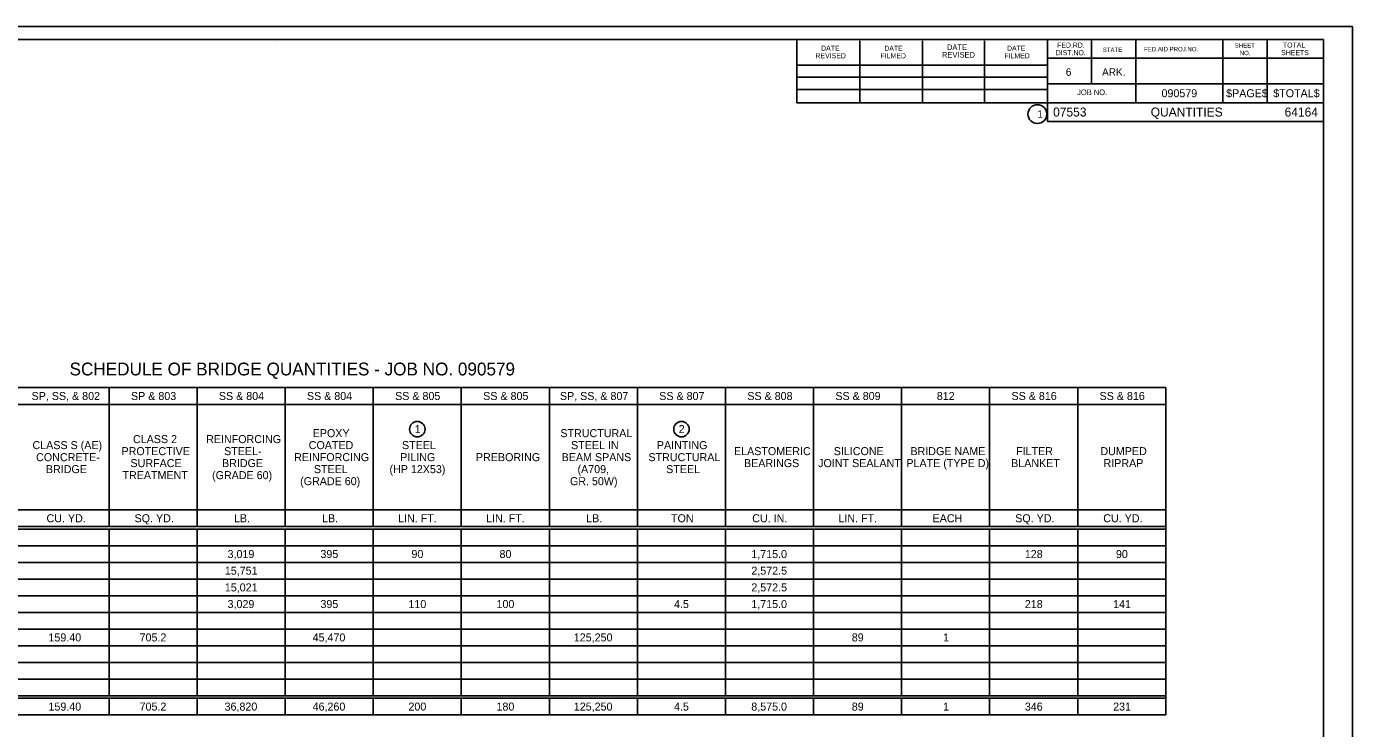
# Model space of a CAD drawing. Extents: x -1.3 to 32.1, y -0.4 to 20.7.
# Drawn here: x 11.36 to 32.07, y 9.78 to 20.75 of the extents above; entities that cross this region are included whole.
import ezdxf

# ---------------------------------------------------------------- set-up
doc = ezdxf.new("R2010")
doc.units = 0
for name, color, linetype in [('Level 1', 7, 'Continuous'), ('Level 1a', 7, 'Continuous'), ('Level 3', 7, 'Continuous'), ('Level 4', 7, 'Continuous'), ('Level 63', 7, 'Continuous'), ('R_Border', 7, 'Continuous')]:
    doc.layers.add(name, color=color, linetype=linetype)

msp = doc.modelspace()

# ---------------------------------------------------------------- linework, layer by layer
at = {"layer": 'Level 1'}
for p, q in [((-0.001, 20.545), (31.617, 20.545)), ((23.391, 19.557), (23.391, 20.545)), ((24.377, 19.557), (24.377, 20.525)), ((25.353, 19.557), (25.353, 20.525)), ((26.321, 19.557), (26.321, 20.525)), ((27.307, 20.545), (27.307, 19.265)), ((27.991, 20.545), (27.991, 19.851)), ((28.685, 20.545), (28.685, 19.557)), ((30.043, 20.545), (30.043, 19.557)), ((30.737, 20.545), (30.737, 19.557)), ((31.617, -0.001), (31.617, 20.545)), ((23.391, 20.143), (27.307, 20.143)), ((31.617, 20.251), (27.307, 20.251)), ((31.617, 20.253), (31.617, 20.253)), ((23.391, 19.957), (27.307, 19.957)), ((23.391, 19.557), (23.391, 19.763)), ((23.391, 19.763), (27.307, 19.763)), ((31.617, 19.851), (27.307, 19.851)), ((31.617, 19.557), (23.391, 19.557))]:
    msp.add_line(p, q, dxfattribs=at)
msp.add_circle((27.147, 19.379), 0.147, dxfattribs=at)
at = {"layer": 'Level 1a'}
msp.add_line((27.307, 19.265), (31.617, 19.265), dxfattribs=at)
at = {"layer": 'Level 3'}
msp.add_line((15.251, 20.519), (15.251, 20.519), dxfattribs=at)
msp.add_line((15.251, 20.519), (15.251, 20.519), dxfattribs=at)
at = {"layer": 'Level 4'}
for p, q in [((29.152, 15.107), (1.652, 15.107)), ((12.652, 15.107), (12.652, 12.937)), ((14.027, 15.107), (14.027, 12.937)), ((15.402, 15.107), (15.402, 12.937)), ((16.777, 15.107), (16.777, 12.937)), ((18.152, 15.107), (18.152, 12.937)), ((19.527, 15.107), (19.527, 12.937)), ((20.902, 15.107), (20.902, 12.937)), ((20.902, 15.107), (20.902, 12.937)), ((22.277, 15.107), (22.277, 12.937)), ((23.652, 15.107), (23.652, 12.937)), ((23.652, 15.107), (23.652, 12.937)), ((25.027, 15.107), (25.027, 12.937)), ((25.027, 15.107), (25.027, 12.937)), ((26.402, 15.107), (26.402, 12.937)), ((26.402, 15.107), (26.402, 12.937)), ((27.777, 15.107), (27.777, 12.937)), ((27.777, 15.107), (27.777, 12.937)), ((29.152, 15.107), (29.152, 9.996)), ((29.152, 14.846), (6.369, 14.846)), ((29.152, 13.198), (6.369, 13.198)), ((29.152, 12.937), (1.652, 12.937)), ((29.152, 12.899), (1.652, 12.899)), ((12.652, 12.899), (12.652, 10.295)), ((14.027, 12.899), (14.027, 10.295)), ((15.402, 12.899), (15.402, 10.295)), ((16.777, 12.899), (16.777, 10.295)), ((18.152, 12.899), (18.152, 10.295)), ((19.527, 12.899), (19.527, 10.295)), ((20.902, 12.899), (20.902, 10.295)), ((20.902, 12.899), (20.902, 10.295)), ((22.277, 12.899), (22.277, 10.295)), ((23.652, 12.899), (23.652, 10.295)), ((23.652, 12.899), (23.652, 10.295)), ((25.027, 12.899), (25.027, 10.295)), ((25.027, 12.899), (25.027, 10.295)), ((26.402, 12.899), (26.402, 10.295)), ((26.402, 12.899), (26.402, 10.295)), ((27.777, 12.899), (27.777, 10.295)), ((27.777, 12.899), (27.777, 10.295)), ((29.152, 12.639), (2.725, 12.639)), ((29.152, 12.378), (2.725, 12.378)), ((29.152, 12.118), (2.725, 12.118)), ((29.152, 11.857), (2.725, 11.857)), ((29.152, 11.857), (2.725, 11.857)), ((29.152, 11.597), (2.725, 11.597)), ((29.152, 11.337), (2.725, 11.337)), ((29.152, 11.076), (2.725, 11.076)), ((29.152, 10.816), (2.725, 10.816)), ((29.152, 10.555), (2.725, 10.555)), ((29.152, 10.295), (1.652, 10.295)), ((29.152, 10.257), (1.652, 10.257)), ((12.652, 10.257), (12.652, 9.996)), ((14.027, 10.257), (14.027, 9.996)), ((15.402, 10.257), (15.402, 9.996)), ((16.777, 10.257), (16.777, 9.996)), ((18.152, 10.257), (18.152, 9.996)), ((19.527, 10.257), (19.527, 9.996)), ((20.902, 10.257), (20.902, 9.996)), ((20.902, 10.257), (20.902, 9.996)), ((22.277, 10.257), (22.277, 9.996)), ((23.652, 10.257), (23.652, 9.996)), ((23.652, 10.257), (23.652, 9.996)), ((25.027, 10.257), (25.027, 9.996)), ((25.027, 10.257), (25.027, 9.996)), ((26.402, 10.257), (26.402, 9.996)), ((26.402, 10.257), (26.402, 9.996)), ((27.777, 10.257), (27.777, 9.996)), ((27.777, 10.257), (27.777, 9.996)), ((29.152, 9.996), (1.652, 9.996))]:
    msp.add_line(p, q, dxfattribs=at)
for centre in [(17.465, 14.459), (21.59, 14.459)]:
    msp.add_circle(centre, 0.121, dxfattribs=at)
at = {"layer": 'Level 63'}
msp.add_lwpolyline([(-1.263, -0.201), (32.067, -0.201), (32.067, 20.747), (-1.263, 20.747)], close=True, dxfattribs=at)

# ---------------------------------------------------------------- texts
at = {"layer": 'Level 1'}
for s, height, p in [('TOTAL', 0.0782, (30.981, 20.417)), ('REVISED', 0.0782, (23.683, 20.251)), ('DATE', 0.0782, (23.771, 20.369)), ('FILMED', 0.0782, (24.699, 20.251)), ('DATE', 0.0782, (24.757, 20.369)), ('REVISED', 0.0879, (25.657, 20.261)), ('DATE', 0.0879, (25.735, 20.379)), ('FILMED', 0.0782, (26.633, 20.251)), ('DATE', 0.0782, (26.673, 20.369)), ('DIST.NO.', 0.0782, (27.435, 20.299)), ('FED.RD.', 0.0782, (27.455, 20.417)), ('STATE', 0.0684, (28.167, 20.349)), ('FED.AID PROJ.NO.', 0.0684, (28.813, 20.359)), ('SHEET', 0.0684, (30.229, 20.417)), ('NO.', 0.0684, (30.307, 20.299)), ('SHEETS', 0.0782, (30.953, 20.299)), ('6', 0.117, (27.591, 19.977)), ('ARK.', 0.1172, (28.157, 19.977)), ('JOB NO.', 0.0879, (27.767, 19.675)), ('1', 0.117, (27.147, 19.321))]:
    msp.add_text(s, height=height, dxfattribs=at).set_placement(p)
at = {"layer": 'Level 4'}
for s, height, p in [('090579', 0.125, (29.085, 19.642)), ('$PAGE$', 0.125, (30.094, 19.642)), ('$TOTAL$', 0.125, (30.83, 19.642)), ('SCHEDULE OF BRIDGE QUANTITIES - JOB NO. 090579', 0.2, (12.036, 15.298)), ('SP, SS, & 802', 0.125, (11.443, 14.914)), ('SP & 803', 0.125, (12.995, 14.914)), ('SS & 804', 0.125, (14.367, 14.914)), ('SS & 804', 0.125, (15.742, 14.914)), ('SS & 805', 0.125, (17.119, 14.914)), ('SS & 805', 0.125, (18.494, 14.914)), ('SP, SS, & 807', 0.125, (19.692, 14.914)), ('SS & 807', 0.125, (21.243, 14.914)), ('SS & 808', 0.125, (22.618, 14.914)), ('SS & 809', 0.125, (23.993, 14.914)), ('812', 0.125, (25.577, 14.914)), ('SS & 816', 0.125, (26.743, 14.914)), ('SS & 816', 0.125, (28.118, 14.914)), ('1', 0.125, (17.425, 14.397)), ('2', 0.125, (21.546, 14.397)), ('CLASS 2', 0.125, (13.026, 14.241)), ('REINFORCING', 0.125, (14.168, 14.241)), ('EPOXY', 0.125, (15.832, 14.334)), ('STRUCTURAL', 0.125, (19.699, 14.334)), ('CLASS S (AE)', 0.125, (11.457, 14.147)), ('CONCRETE-', 0.125, (11.514, 13.959)), ('PROTECTIVE', 0.125, (12.847, 14.053)), ('STEEL-', 0.125, (14.449, 14.053)), ('REINFORCING', 0.125, (15.543, 13.959)), ('COATED', 0.125, (15.77, 14.147)), ('PILING', 0.125, (17.198, 13.959)), ('STEEL', 0.125, (17.226, 14.147)), ('PREBORING', 0.125, (18.381, 13.959)), ('BEAM SPANS', 0.125, (19.719, 13.959)), ('STEEL IN', 0.125, (19.866, 14.147)), ('STRUCTURAL', 0.125, (21.074, 13.959)), ('PAINTING', 0.125, (21.206, 14.147)), ('ELASTOMERIC', 0.125, (22.41, 14.053)), ('SILICONE', 0.125, (23.968, 14.053)), ('BRIDGE NAME', 0.125, (25.165, 14.053)), ('FILTER', 0.125, (26.815, 14.053)), ('DUMPED', 0.125, (28.131, 14.053)), ('BRIDGE', 0.125, (11.666, 13.772)), ('SURFACE', 0.125, (12.987, 13.866)), ('BRIDGE', 0.125, (14.416, 13.866)), ('STEEL', 0.125, (15.851, 13.772)), ('(HP 12X53)', 0.125, (17.031, 13.772)), ('(A709,', 0.125, (19.967, 13.772)), ('STEEL', 0.125, (21.351, 13.772)), ('BEARINGS', 0.125, (22.566, 13.866)), ('JOINT SEALANT', 0.125, (23.724, 13.866)), ('PLATE (TYPE D)', 0.125, (25.102, 13.866)), ('BLANKET', 0.125, (26.737, 13.866)), ('RIPRAP', 0.125, (28.18, 13.866)), ('TREATMENT', 0.125, (12.862, 13.678)), ('(GRADE 60)', 0.125, (14.261, 13.678)), ('(GRADE 60)', 0.125, (15.636, 13.584)), ('GR. 50W)', 0.125, (19.849, 13.584)), ('CU. YD.', 0.125, (11.676, 13.005)), ('SQ. YD.', 0.125, (13.051, 13.005)), ('LB.', 0.125, (14.603, 13.005)), ('LB.', 0.125, (15.978, 13.005)), ('LIN. FT.', 0.125, (17.165, 13.005)), ('LIN. FT.', 0.125, (18.54, 13.005)), ('LB.', 0.125, (20.103, 13.005)), ('TON', 0.125, (21.427, 13.005)), ('CU. IN.', 0.125, (22.695, 13.005)), ('LIN. FT.', 0.125, (24.04, 13.005)), ('EACH', 0.125, (25.511, 13.005)), ('SQ. YD.', 0.125, (26.801, 13.005)), ('CU. YD.', 0.125, (28.176, 13.005)), ('3,019', 0.125, (14.503, 12.446)), ('395', 0.125, (15.953, 12.446)), ('90', 0.125, (17.374, 12.446)), ('80', 0.125, (18.749, 12.446)), ('1,715.0', 0.125, (22.68, 12.446)), ('128', 0.125, (26.951, 12.446)), ('90', 0.125, (28.374, 12.446)), ('15,751', 0.125, (14.46, 12.186)), ('2,572.5', 0.125, (22.681, 12.186)), ('15,021', 0.125, (14.46, 11.925)), ('2,572.5', 0.125, (22.681, 11.925)), ('3,029', 0.125, (14.503, 11.665)), ('395', 0.125, (15.953, 11.665)), ('110', 0.125, (17.327, 11.665)), ('100', 0.125, (18.702, 11.665)), ('4.5', 0.125, (21.474, 11.665)), ('1,715.0', 0.125, (22.68, 11.665)), ('218', 0.125, (26.951, 11.665)), ('141', 0.125, (28.33, 11.665)), ('159.40', 0.125, (11.706, 11.144)), ('705.2', 0.125, (13.129, 11.144)), ('45,470', 0.125, (15.831, 11.144)), ('125,250', 0.125, (19.909, 11.144)), ('89', 0.125, (24.249, 11.144)), ('1', 0.125, (25.675, 11.144)), ('159.40', 0.125, (11.706, 10.064)), ('705.2', 0.125, (13.129, 10.064)), ('36,820', 0.125, (14.456, 10.064)), ('46,260', 0.125, (15.831, 10.064)), ('200', 0.125, (17.327, 10.064)), ('180', 0.125, (18.702, 10.064)), ('125,250', 0.125, (19.909, 10.064)), ('4.5', 0.125, (21.474, 10.064)), ('8,575.0', 0.125, (22.68, 10.064)), ('89', 0.125, (24.249, 10.064)), ('1', 0.125, (25.675, 10.064)), ('346', 0.125, (26.951, 10.064)), ('231', 0.125, (28.33, 10.064))]:
    msp.add_text(s, height=height, dxfattribs=at).set_placement(p)
at = {"layer": 'R_Border'}
for s, p in [('07553', (27.393, 19.341)), ('QUANTITIES', (28.917, 19.341)), ('64164', (31.008, 19.341))]:
    msp.add_text(s, height=0.14, dxfattribs=at).set_placement(p)

doc.saveas('drawing.dxf')
